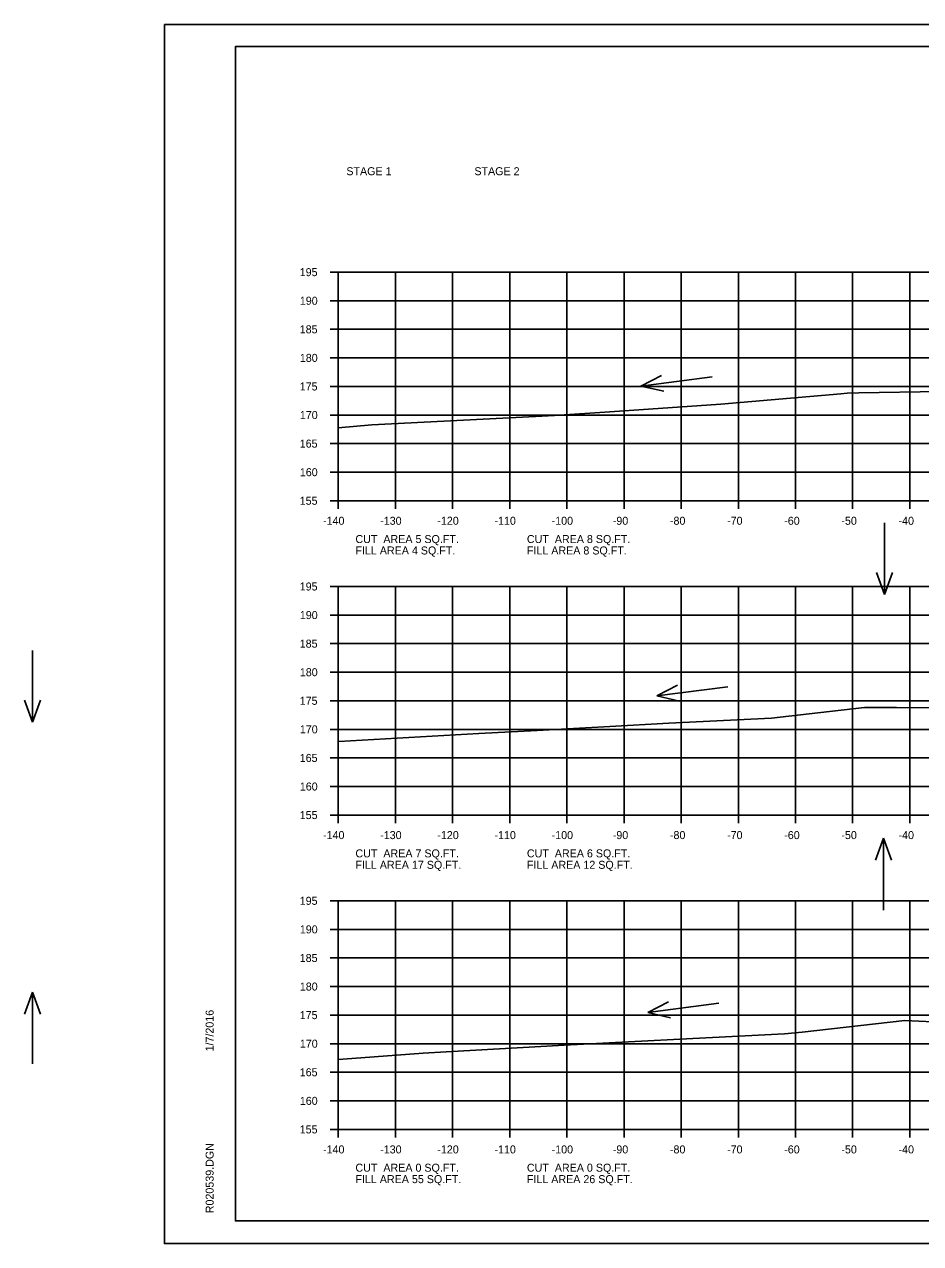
# Model space of a CAD drawing. Extents: x 915787 to 919910, y 133456 to 136717.
# Drawn here: x 916219.1 to 916375.9, y 136016.1 to 136229.4 of the extents above; entities that cross this region are included whole.
import ezdxf

# ---------------------------------------------------------------- set-up
doc = ezdxf.new("R2010")
doc.units = 0
for name, color, linetype in [('R_Axis', 7, 'Continuous'), ('R_Axis Annot', 7, 'Continuous'), ('R_Border', 7, 'Continuous'), ('R_Border Notes', 7, 'Continuous'), ('R_Exist Surface', 7, 'Continuous'), ('R_Grid', 7, 'Continuous'), ('R_No Plot', 7, 'Continuous'), ('R_Water Annot', 7, 'Continuous')]:
    doc.layers.add(name, color=color, linetype=linetype)

msp = doc.modelspace()

# ---------------------------------------------------------------- linework, layer by layer
at = {"layer": 'R_Axis'}
for p, q in [((916272.58, 136186.07), (916273.98, 136186.07)), ((916273.98, 136146.07), (916273.98, 136186.07)), ((916272.58, 136181.07), (916273.98, 136181.07)), ((916272.58, 136176.07), (916273.98, 136176.07)), ((916272.58, 136171.07), (916273.98, 136171.07)), ((916272.58, 136166.07), (916273.98, 136166.07)), ((916272.58, 136161.07), (916273.98, 136161.07)), ((916272.58, 136156.07), (916273.98, 136156.07)), ((916272.58, 136151.07), (916273.98, 136151.07)), ((916272.58, 136146.07), (916273.98, 136146.07)), ((916273.98, 136146.07), (916553.98, 136146.07)), ((916273.98, 136144.67), (916273.98, 136146.07)), ((916283.98, 136144.67), (916283.98, 136146.07)), ((916293.98, 136144.67), (916293.98, 136146.07)), ((916303.98, 136144.67), (916303.98, 136146.07)), ((916313.98, 136144.67), (916313.98, 136146.07)), ((916323.98, 136144.67), (916323.98, 136146.07)), ((916333.98, 136144.67), (916333.98, 136146.07)), ((916343.98, 136144.67), (916343.98, 136146.07)), ((916353.98, 136144.67), (916353.98, 136146.07)), ((916363.98, 136144.67), (916363.98, 136146.07)), ((916373.98, 136144.67), (916373.98, 136146.07)), ((916272.58, 136131.07), (916273.98, 136131.07)), ((916273.98, 136091.07), (916273.98, 136131.07)), ((916272.58, 136126.07), (916273.98, 136126.07)), ((916272.58, 136121.07), (916273.98, 136121.07)), ((916272.58, 136116.07), (916273.98, 136116.07)), ((916272.58, 136111.07), (916273.98, 136111.07)), ((916272.58, 136106.07), (916273.98, 136106.07)), ((916272.58, 136101.07), (916273.98, 136101.07)), ((916272.58, 136096.07), (916273.98, 136096.07)), ((916272.58, 136091.07), (916273.98, 136091.07)), ((916273.98, 136091.07), (916553.98, 136091.07)), ((916273.98, 136089.67), (916273.98, 136091.07)), ((916283.98, 136089.67), (916283.98, 136091.07)), ((916293.98, 136089.67), (916293.98, 136091.07)), ((916303.98, 136089.67), (916303.98, 136091.07)), ((916313.98, 136089.67), (916313.98, 136091.07)), ((916323.98, 136089.67), (916323.98, 136091.07)), ((916333.98, 136089.67), (916333.98, 136091.07)), ((916343.98, 136089.67), (916343.98, 136091.07)), ((916353.98, 136089.67), (916353.98, 136091.07)), ((916363.98, 136089.67), (916363.98, 136091.07)), ((916373.98, 136089.67), (916373.98, 136091.07)), ((916272.58, 136076.07), (916273.98, 136076.07)), ((916273.98, 136036.07), (916273.98, 136076.07)), ((916272.58, 136071.07), (916273.98, 136071.07)), ((916272.58, 136066.07), (916273.98, 136066.07)), ((916272.58, 136061.07), (916273.98, 136061.07)), ((916272.58, 136056.07), (916273.98, 136056.07)), ((916272.58, 136051.07), (916273.98, 136051.07)), ((916272.58, 136046.07), (916273.98, 136046.07)), ((916272.58, 136041.07), (916273.98, 136041.07)), ((916272.58, 136036.07), (916273.98, 136036.07)), ((916273.98, 136036.07), (916553.98, 136036.07)), ((916273.98, 136034.67), (916273.98, 136036.07)), ((916283.98, 136034.67), (916283.98, 136036.07)), ((916293.98, 136034.67), (916293.98, 136036.07)), ((916303.98, 136034.67), (916303.98, 136036.07)), ((916313.98, 136034.67), (916313.98, 136036.07)), ((916323.98, 136034.67), (916323.98, 136036.07)), ((916333.98, 136034.67), (916333.98, 136036.07)), ((916343.98, 136034.67), (916343.98, 136036.07)), ((916353.98, 136034.67), (916353.98, 136036.07)), ((916363.98, 136034.67), (916363.98, 136036.07)), ((916373.98, 136034.67), (916373.98, 136036.07))]:
    msp.add_line(p, q, dxfattribs=at)
at = {"layer": 'R_Border'}
for p, q in [((916255.98, 136225.53), (916572.16, 136225.53)), ((916255.98, 136020.07), (916255.98, 136225.53)), ((916255.98, 136020.07), (916255.98, 136020.07)), ((916572.16, 136020.07), (916255.98, 136020.07))]:
    msp.add_line(p, q, dxfattribs=at)
at = {"layer": 'R_Exist Surface'}
for points in [[(916273.98, 136158.83), (916279.83, 136159.36), (916308.49, 136160.84), (916311.81, 136161.01), (916321.52, 136161.65), (916340.89, 136162.95), (916361.9, 136164.8), (916363.01, 136164.9), (916365.06, 136164.93), (916379.38, 136165.2)], [(916273.98, 136103.94), (916274.06, 136103.94), (916282.23, 136104.41), (916298.58, 136105.35), (916308.77, 136105.89), (916321.47, 136106.59), (916331.79, 136107.13), (916349.8, 136108.05), (916356.36, 136108.77), (916366.03, 136109.9), (916371.67, 136109.9), (916379.14, 136109.82)], [(916273.98, 136048.32), (916277.93, 136048.6), (916288.82, 136049.42), (916292.87, 136049.64), (916310.49, 136050.66), (916313.53, 136050.83), (916336.03, 136051.97), (916352.07, 136052.78), (916355.13, 136053.11), (916373.11, 136055.1), (916380.52, 136054.78)]]:
    msp.add_lwpolyline(points, dxfattribs=at)
at = {"layer": 'R_Grid'}
for p, q in [((916273.98, 136186.07), (916553.98, 136186.07)), ((916273.98, 136146.07), (916273.98, 136186.07)), ((916283.98, 136146.07), (916283.98, 136186.07)), ((916293.98, 136146.07), (916293.98, 136186.07)), ((916303.98, 136146.07), (916303.98, 136186.07)), ((916313.98, 136146.07), (916313.98, 136186.07)), ((916323.98, 136146.07), (916323.98, 136186.07)), ((916333.98, 136146.07), (916333.98, 136186.07)), ((916343.98, 136146.07), (916343.98, 136186.07)), ((916353.98, 136146.07), (916353.98, 136186.07)), ((916363.98, 136146.07), (916363.98, 136186.07)), ((916373.98, 136146.07), (916373.98, 136186.07)), ((916273.98, 136181.07), (916553.98, 136181.07)), ((916273.98, 136176.07), (916553.98, 136176.07)), ((916273.98, 136171.07), (916553.98, 136171.07)), ((916273.98, 136166.07), (916553.98, 136166.07)), ((916273.98, 136161.07), (916553.98, 136161.07)), ((916273.98, 136156.07), (916553.98, 136156.07)), ((916273.98, 136151.07), (916553.98, 136151.07)), ((916273.98, 136146.07), (916553.98, 136146.07)), ((916273.98, 136131.07), (916553.98, 136131.07)), ((916273.98, 136091.07), (916273.98, 136131.07)), ((916283.98, 136091.07), (916283.98, 136131.07)), ((916293.98, 136091.07), (916293.98, 136131.07)), ((916303.98, 136091.07), (916303.98, 136131.07)), ((916313.98, 136091.07), (916313.98, 136131.07)), ((916323.98, 136091.07), (916323.98, 136131.07)), ((916333.98, 136091.07), (916333.98, 136131.07)), ((916343.98, 136091.07), (916343.98, 136131.07)), ((916353.98, 136091.07), (916353.98, 136131.07)), ((916363.98, 136091.07), (916363.98, 136131.07)), ((916373.98, 136091.07), (916373.98, 136131.07)), ((916273.98, 136126.07), (916553.98, 136126.07)), ((916273.98, 136121.07), (916553.98, 136121.07)), ((916273.98, 136116.07), (916553.98, 136116.07)), ((916273.98, 136111.07), (916553.98, 136111.07)), ((916273.98, 136106.07), (916553.98, 136106.07)), ((916273.98, 136101.07), (916553.98, 136101.07)), ((916273.98, 136096.07), (916553.98, 136096.07)), ((916273.98, 136091.07), (916553.98, 136091.07)), ((916273.98, 136076.07), (916553.98, 136076.07)), ((916273.98, 136036.07), (916273.98, 136076.07)), ((916283.98, 136036.07), (916283.98, 136076.07)), ((916293.98, 136036.07), (916293.98, 136076.07)), ((916303.98, 136036.07), (916303.98, 136076.07)), ((916313.98, 136036.07), (916313.98, 136076.07)), ((916323.98, 136036.07), (916323.98, 136076.07)), ((916333.98, 136036.07), (916333.98, 136076.07)), ((916343.98, 136036.07), (916343.98, 136076.07)), ((916353.98, 136036.07), (916353.98, 136076.07)), ((916363.98, 136036.07), (916363.98, 136076.07)), ((916373.98, 136036.07), (916373.98, 136076.07)), ((916273.98, 136071.07), (916553.98, 136071.07)), ((916273.98, 136066.07), (916553.98, 136066.07)), ((916273.98, 136061.07), (916553.98, 136061.07)), ((916273.98, 136056.07), (916553.98, 136056.07)), ((916273.98, 136051.07), (916553.98, 136051.07)), ((916273.98, 136046.07), (916553.98, 136046.07)), ((916273.98, 136041.07), (916553.98, 136041.07)), ((916273.98, 136036.07), (916553.98, 136036.07))]:
    msp.add_line(p, q, dxfattribs=at)
at = {"layer": 'R_No Plot'}
for p, q in [((916243.57, 136229.43), (916576.91, 136229.43)), ((916243.57, 136016.09), (916576.91, 136016.09))]:
    msp.add_line(p, q, dxfattribs=at)
for points in [[(916243.57, 136229.43), (916576.91, 136229.43), (916576.91, 136016.09), (916243.57, 136016.09)], [(916489.9, 136225.53), (916489.9, 136215.65), (916525.63, 136215.65), (916525.63, 136212.73), (916548.83, 136212.73), (916548.83, 136189.52), (916572.16, 136189.52), (916572.16, 136020.07), (916255.98, 136020.07), (916255.98, 136225.53)]]:
    msp.add_lwpolyline(points, close=True, dxfattribs=at)
at = {"layer": 'R_Water Annot'}
for p, q in [((916326.93, 136166.13), (916330.56, 136168.01)), ((916339.39, 136167.76), (916326.93, 136166.13)), ((916326.93, 136166.13), (916330.92, 136165.24)), ((916369.57, 136142.21), (916369.57, 136129.64)), ((916369.57, 136129.64), (916368.17, 136133.49)), ((916369.57, 136129.64), (916370.97, 136133.49)), ((916220.45, 136119.89), (916220.45, 136107.32)), ((916329.7, 136111.91), (916333.33, 136113.8)), ((916342.16, 136113.54), (916329.7, 136111.91)), ((916329.7, 136111.91), (916333.69, 136111.02)), ((916220.45, 136107.32), (916219.05, 136111.16)), ((916220.45, 136107.32), (916221.85, 136111.16)), ((916369.4, 136087.02), (916368, 136083.17)), ((916369.4, 136074.45), (916369.4, 136087.02)), ((916369.4, 136087.02), (916370.8, 136083.17)), ((916220.45, 136060.1), (916219.05, 136056.26)), ((916220.45, 136047.53), (916220.45, 136060.1)), ((916220.45, 136060.1), (916221.85, 136056.26)), ((916328.12, 136056.51), (916331.75, 136058.39)), ((916340.58, 136058.14), (916328.12, 136056.51)), ((916328.12, 136056.51), (916332.11, 136055.62))]:
    msp.add_line(p, q, dxfattribs=at)

# ---------------------------------------------------------------- texts
at = {"layer": 'R_Axis Annot'}
for s, p in [('195', (916267.23, 136185.37)), ('190', (916267.25, 136180.37)), ('185', (916267.23, 136175.37)), ('180', (916267.25, 136170.37)), ('175', (916267.23, 136165.37)), ('170', (916267.25, 136160.37)), ('165', (916267.23, 136155.37)), ('160', (916267.25, 136150.37)), ('155', (916267.23, 136145.37)), ('-140', (916271.31, 136141.87)), ('-130', (916281.31, 136141.87)), ('-120', (916291.31, 136141.87)), ('-110', (916301.31, 136141.87)), ('-100', (916311.31, 136141.87)), ('-90', (916322.01, 136141.87)), ('-80', (916332.01, 136141.87)), ('-70', (916342.01, 136141.87)), ('-60', (916352.01, 136141.87)), ('-50', (916362.01, 136141.87)), ('-40', (916372.01, 136141.87)), ('195', (916267.23, 136130.37)), ('190', (916267.25, 136125.37)), ('185', (916267.23, 136120.37)), ('180', (916267.25, 136115.37)), ('175', (916267.23, 136110.37)), ('170', (916267.25, 136105.37)), ('165', (916267.23, 136100.37)), ('160', (916267.25, 136095.37)), ('155', (916267.23, 136090.37)), ('-140', (916271.31, 136086.87)), ('-130', (916281.31, 136086.87)), ('-120', (916291.31, 136086.87)), ('-110', (916301.31, 136086.87)), ('-100', (916311.31, 136086.87)), ('-90', (916322.01, 136086.87)), ('-80', (916332.01, 136086.87)), ('-70', (916342.01, 136086.87)), ('-60', (916352.01, 136086.87)), ('-50', (916362.01, 136086.87)), ('-40', (916372.01, 136086.87)), ('195', (916267.23, 136075.37)), ('190', (916267.25, 136070.37)), ('185', (916267.23, 136065.37)), ('180', (916267.25, 136060.37)), ('175', (916267.23, 136055.37)), ('170', (916267.25, 136050.37)), ('165', (916267.23, 136045.37)), ('160', (916267.25, 136040.37)), ('155', (916267.23, 136035.37)), ('-140', (916271.31, 136031.87)), ('-130', (916281.31, 136031.87)), ('-120', (916291.31, 136031.87)), ('-110', (916301.31, 136031.87)), ('-100', (916311.31, 136031.87)), ('-90', (916322.01, 136031.87)), ('-80', (916332.01, 136031.87)), ('-70', (916342.01, 136031.87)), ('-60', (916352.01, 136031.87)), ('-50', (916362.01, 136031.87)), ('-40', (916372.01, 136031.87))]:
    msp.add_text(s, height=1.4, dxfattribs=at).set_placement(p)
at = {"layer": 'R_Border'}
for s, p in [('1/7/2016', (916252.17, 136049.71)), ('R020539.DGN', (916252.17, 136021.4))]:
    msp.add_text(s, height=1.4, rotation=90, dxfattribs=at).set_placement(p)
at = {"layer": 'R_Border Notes'}
for s, p in [('STAGE 1', (916275.39, 136203.03)), ('STAGE 2', (916297.79, 136203.03)), ('CUT  AREA 5 SQ.FT.', (916276.98, 136138.67)), ('CUT  AREA 8 SQ.FT.', (916306.98, 136138.67)), ('FILL AREA 4 SQ.FT.', (916276.98, 136136.67)), ('FILL AREA 8 SQ.FT.', (916306.98, 136136.67)), ('CUT  AREA 7 SQ.FT.', (916276.98, 136083.67)), ('CUT  AREA 6 SQ.FT.', (916306.98, 136083.67)), ('FILL AREA 17 SQ.FT.', (916276.98, 136081.67)), ('FILL AREA 12 SQ.FT.', (916306.98, 136081.67)), ('CUT  AREA 0 SQ.FT.', (916276.98, 136028.67)), ('CUT  AREA 0 SQ.FT.', (916306.98, 136028.67)), ('FILL AREA 55 SQ.FT.', (916276.98, 136026.67)), ('FILL AREA 26 SQ.FT.', (916306.98, 136026.67))]:
    msp.add_text(s, height=1.4, dxfattribs=at).set_placement(p)

doc.saveas('drawing.dxf')
